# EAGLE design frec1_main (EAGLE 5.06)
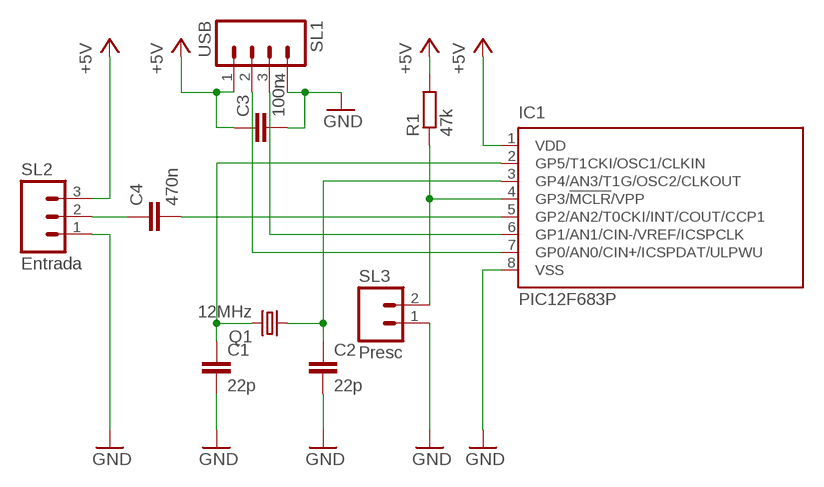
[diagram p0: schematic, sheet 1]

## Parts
C1  22p  C-EU050-024X044  [C050-024X044]
C2  22p  C-EU050-024X044  [C050-024X044]
C3  100n  C-EU050-030X075  [C050-030X075]
C4  470n  C-EU050-030X075  [C050-030X075]
IC1  PIC12F683P  [DIL8]
Q1  12MHz  CRYSTALHC49U70  [HC49U70]
R1  47k  R-EU_0207/10  [0207/10]
SL1  USB  M04  [04P]
SL2  Entrada  M03  [03P]
SL3  Presc  M02  [02P]

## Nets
+5V: C3.1 IC1.1(VDD) R1.2 SL1.1 SL2.3
GND: C1.2 C2.2 C3.2 IC1.8(VSS) SL1.4 SL2.1 SL3.1
N$1: C4.1 SL2.2
N$2: C4.2 IC1.5(GP2/AN2/T0CKI/INT/COUT/CCP1)
N$3: IC1.4(GP3/!MCLR!/VPP) R1.1 SL3.2
N$4: C1.1 IC1.2(GP5/T1CKI/OSC1/CLKIN) Q1.2
N$5: C2.1 IC1.3(GP4/AN3/T1G/OSC2/CLKOUT) Q1.1
N$6: IC1.6(GP1/AN1/CIN-/VREF/ICSPCLK) SL1.3
N$7: IC1.7(GP0/AN0/CIN+/ICSPDAT/ULPWU) SL1.2

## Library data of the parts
C1-C4 = rcl:C-EU: CAPACITOR, European symbol
IC1 = microchip:PIC12F683: 8-Pin Flash-Based, 8-Bit CMOS Microcontrollers with nanoWatt Technology Source: http://ww1.microchip.com/downloads/en/DeviceDoc/41211D_.pdf
Q1 = crystal:CRYSTAL: CRYSTAL
R1 = resistor:R-EU_: RESISTOR, European symbol
SL1 = con-amp-quick:M04: AMP QUICK CONNECTOR
SL2 = con-amp-quick:M03: AMP QUICK CONNECTOR
SL3 = con-amp-quick:M02: AMP QUICK CONNECTOR

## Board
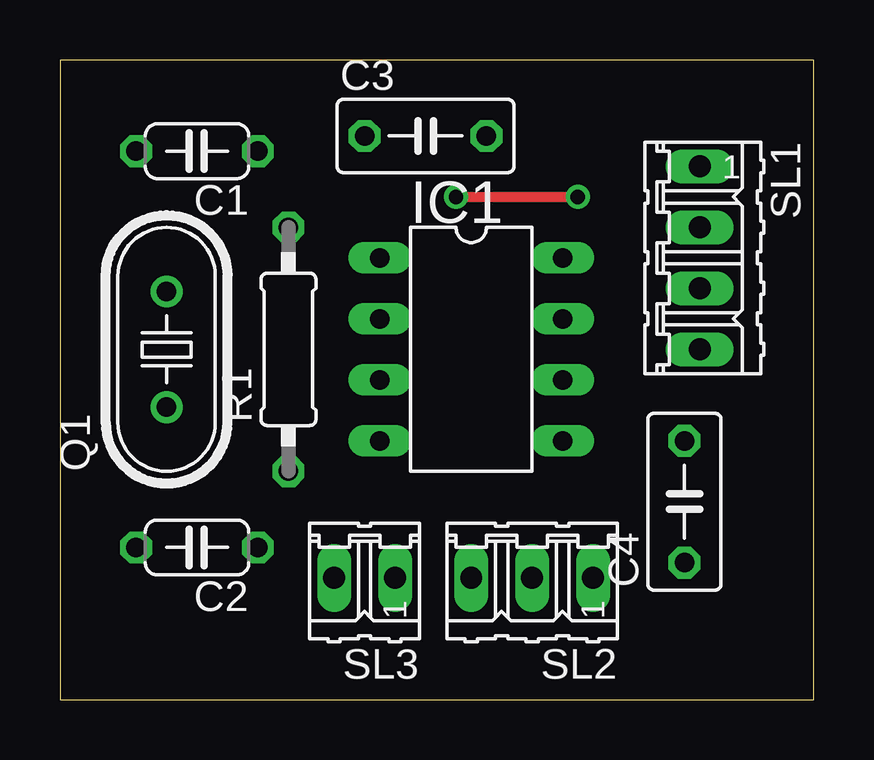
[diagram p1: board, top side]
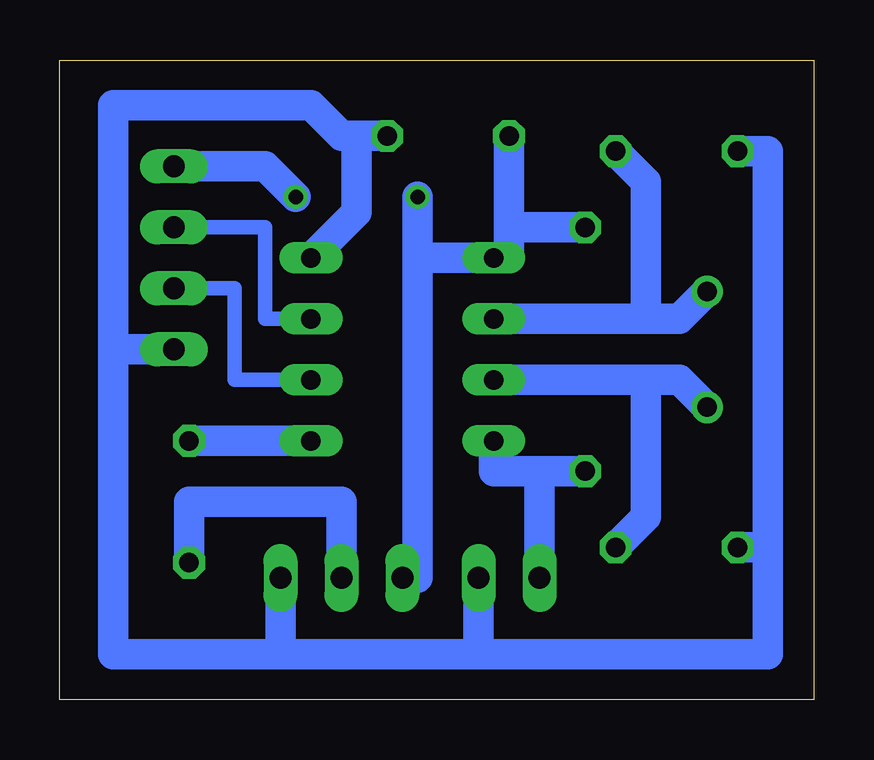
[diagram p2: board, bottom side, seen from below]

Size 31.42 x 26.66 mm. Coordinates in mm from the lower left corner, seen from the top.
Outline: 0,0 31.42,0 31.42,26.66 0,26.66 0,0
Copper layers (1*16): Top 0.035mm / dielectric 1.5mm / Bottom 0.035mm
Design rules "default": minimum track width 10mil, minimum drill 24mil, track to track 8mil, track to pad 8mil, pad to pad 8mil, via to via 8mil, smd to smd 8mil, copper to edge 40mil, drill to drill 8mil, minimum pad ring 10mil, minimum via ring 8mil, stop-mask expansion 4mil, vias tented up to drill 0mil, thermal gap 10mil

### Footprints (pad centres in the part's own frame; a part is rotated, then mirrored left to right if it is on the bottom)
C050-024X044 = drill 0.813 octagon: 1 -2.54,0; 2 2.54,0
C050-030X075 = drill 0.813 octagon: 1 -2.54,0; 2 2.54,0
DIL8 = drill 0.813 long: 1 -3.81,-3.81; 2 -1.27,-3.81; 3 1.27,-3.81; 4 3.81,-3.81; 5 3.81,3.81; 6 1.27,3.81; 7 -1.27,3.81; 8 -3.81,3.81
HC49U70 = drill 0.813 round: 1 -2.413,0; 2 2.413,0
0207/10 = drill 0.813 octagon: 1 -5.08,0; 2 5.08,0
04P = drill 0.914 long: 1 -3.81,0; 2 -1.27,0; 3 1.27,0; 4 3.81,0
03P = drill 0.914 long: 1 -2.54,0; 2 0,0; 3 2.54,0
02P = drill 0.914 long: 1 -1.27,0; 2 1.27,0

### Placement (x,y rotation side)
C1  5.71,22.86 180 top
C2  5.71,6.35 180 top
C3  15.24,23.5 0 top
C4  26.04,8.26 90 top
IC1  17.15,14.61 270 top
Q1  4.45,14.61 90 top
R1  9.53,14.61 90 top
SL1  26.67,18.42 270 top
SL2  19.69,5.08 180 top
SL3  12.7,5.08 180 top

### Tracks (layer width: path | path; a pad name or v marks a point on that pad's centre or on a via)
+5V  (via drill 0.6)
  Top 0.406: v16.51,20.96 v21.59,20.96
  Bottom 1.27: SL2.3 16.51,5.08 16.51,18.42 | SL1.1 22.86,22.23 v21.59,20.96 | 12.7,18.42 12.7,19.69 | 12.7,19.69 12.7,20.96 | 12.7,20.96 C3.1 | 12.7,18.42 IC1.1 | 12.7,19.69 R1.2 | 16.51,18.42 v16.51,20.96 | 12.7,18.42 12.7,20.96 | 16.51,18.42 12.7,18.42
GND
  Bottom 1.27: C1.2 1.91,22.86 1.91,6.35 | 1.91,6.35 C2.2 | 1.91,6.35 1.91,1.91 13.97,1.91 | 13.97,1.91 22.23,1.91 | 22.23,1.91 29.21,1.91 29.21,14.61 | 29.21,14.61 29.21,24.77 20.96,24.77 19.69,23.5 19.05,23.5 | 13.97,1.91 SL3.1 | 22.23,1.91 SL2.1 | 29.21,14.61 SL1.4 | 19.05,23.5 C3.2 | IC1.8 19.05,20.32 19.05,23.5
N$1
  Bottom 1.27: SL2.2 19.69,8.26 26.04,8.26 C4.1
N$2
  Bottom 1.27: IC1.5 C4.2
N$3
  Bottom 1.27: 11.43,9.53 R1.1 | 11.43,9.53 13.33,9.53 IC1.4 | SL3.2 11.43,9.53
N$4
  Bottom 1.27: 6.98,15.88 5.59,15.88 Q1.2 | 6.98,15.88 IC1.2 | C1.1 6.98,21.59 6.98,15.88
N$5
  Bottom 1.27: 6.98,13.33 5.59,13.33 Q1.1 | 6.98,13.33 IC1.3 | C2.1 6.98,7.62 6.98,13.33
N$6
  Bottom 0.61: SL1.3 24.13,17.15 24.13,13.33 IC1.6
N$7
  Bottom 0.61: SL1.2 22.86,19.69 22.86,15.88 IC1.7
N$9  (via drill 0.6)
  other vias: 21.59,20.96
